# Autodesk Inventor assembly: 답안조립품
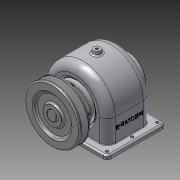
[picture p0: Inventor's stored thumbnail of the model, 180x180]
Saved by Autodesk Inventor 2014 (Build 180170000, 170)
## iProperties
Created: 2015-09
Part Number: 답안조립품
Document SubType Name: Assembly
Designer: Administrator
Author: Administrator
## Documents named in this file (14)
- C:\Users\Administrator\Desktop\450907V1044\답안조립품.iam
- C:\Users\Administrator\Desktop\450907V1044\1-본체.ipt
- C:\Users\Administrator\Desktop\450907V1044\V-벨트풀리.ipt
- C:\Users\Administrator\Desktop\450907V1044\뒤커버.ipt
- C:\Users\Administrator\Desktop\450907V1044\멈춤나사 - M4x10.ipt
- C:\Users\Administrator\Desktop\450907V1044\베어링 6203.ipt
- C:\Users\Administrator\Desktop\450907V1044\볼트 M3 x 8.ipt
- C:\Users\Administrator\Desktop\450907V1044\볼트 M3 x 10.ipt
- C:\Users\Administrator\Desktop\450907V1044\스퍼기어.ipt
- C:\Users\Administrator\Desktop\450907V1044\앞커버.ipt
- C:\Users\Administrator\Desktop\450907V1044\오일 실 17 32 8.ipt
- C:\Users\Administrator\Desktop\450907V1044\축.ipt
- C:\Users\Administrator\Desktop\450907V1044\키 - 5 x 5 x 18.ipt
- C:\Users\Administrator\Desktop\450907V1044\키 - 6 x 6 x 22.ipt
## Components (10 placed, 4 different names)
1. 1-본체:1 — 각도:1, 각도:2
2. V-벨트풀리:1
3. ISO 4762 M3 x 8:1 — 각도:1
4. ISO 4762 M3 x 8:2
5. ISO 4762 M3 x 8:3
6. ISO 4762 M3 x 8:4
7. ISO 4762 M3 x 10:1 — 각도:2
8. ISO 4762 M3 x 10:2
9. ISO 4762 M3 x 10:3
10. ISO 4762 M3 x 10:4
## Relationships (2: Angle 2)
- 각도:1 [Angle]: 1-본체:1 ↔ ISO 4762 M3 x 8:1
- 각도:2 [Angle]: 1-본체:1 ↔ ISO 4762 M3 x 10:1
